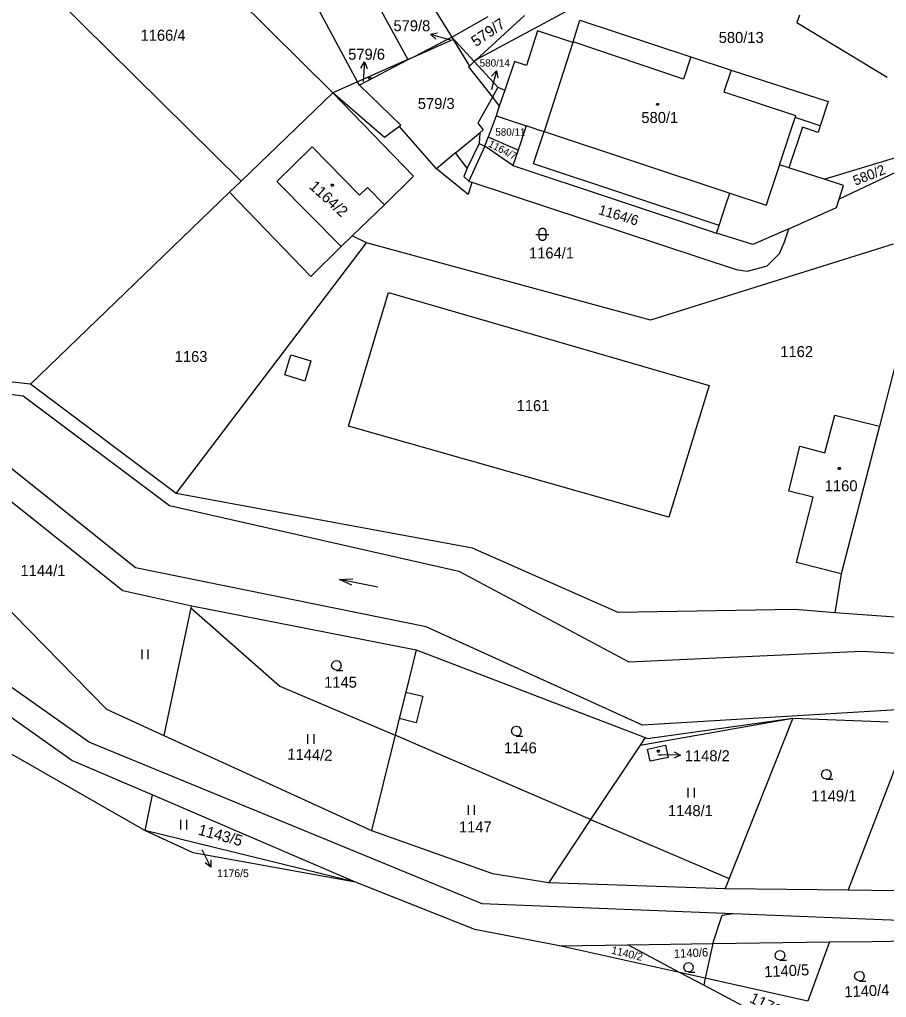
# Model space of a CAD drawing. Extents: x -621797 to -620972, y -1175539 to -1174697.
# Drawn here: x -621726 to -621592, y -1175130.5 to -1174979.5 of the extents above; entities that cross this region are included whole.
import ezdxf

# ---------------------------------------------------------------- set-up
doc = ezdxf.new("R2010")
doc.units = 0
for name, color, linetype in [('INZ mimo EON - nadz', 7, 'Continuous'), ('Rozvod plynu EON', 7, 'Continuous'), ('SDEL EON', 7, 'Continuous'), ('SDEL EON - popis', 7, 'Continuous'), ('Silnoproud EON', 7, 'Continuous'), ('Silnoproud EON - popis', 7, 'Continuous')]:
    doc.layers.add(name, color=color, linetype=linetype)

msp = doc.modelspace()

# ---------------------------------------------------------------- linework, layer by layer
at = {"layer": 'INZ mimo EON - nadz'}
for p, q in [((-621662.497, -1174981.741), (-621659.62, -1174982.59)), ((-621659.5, -1174982.63), (-621659.62, -1174982.59)), ((-621672.715, -1174986.035), (-621672.88, -1174989.03)), ((-621652.304, -1174987.405), (-621653.09, -1174990.3)), ((-621672.88, -1174989.06), (-621672.88, -1174989.03)), ((-621653.09, -1174990.32), (-621653.09, -1174990.3)), ((-621627.26, -1175093.06), (-621626.86, -1175093.07)), ((-621623.861, -1175093.125), (-621626.86, -1175093.07)), ((-621696.438, -1175110.413), (-621697.8, -1175107.74))]:
    msp.add_line(p, q, dxfattribs=at)
for points in [[(-621661.68, -1174982.504), (-621662.497, -1174981.741), (-621661.397, -1174981.545)], [(-621673.269, -1174987.005), (-621672.715, -1174986.035), (-621672.27, -1174987.061)], [(-621653.048, -1174988.239), (-621652.304, -1174987.405), (-621652.083, -1174988.501)], [(-621624.851, -1175092.607), (-621623.861, -1175093.125), (-621624.87, -1175093.607)], [(-621696.446, -1175109.295), (-621696.438, -1175110.413), (-621697.337, -1175109.749)]]:
    msp.add_lwpolyline(points, dxfattribs=at)
at = {"layer": 'Rozvod plynu EON'}
for points in [[(-621671.82, -1174988.38), (-621671.73, -1174988.53), (-621671.82, -1174988.68), (-621672, -1174988.68), (-621672.09, -1174988.53), (-621672, -1174988.38)], [(-621627.33, -1174992.44), (-621627.24, -1174992.59), (-621627.33, -1174992.74), (-621627.51, -1174992.74), (-621627.6, -1174992.59), (-621627.51, -1174992.44)], [(-621677.55, -1175004.93), (-621677.46, -1175005.08), (-621677.55, -1175005.23), (-621677.73, -1175005.23), (-621677.82, -1175005.08), (-621677.73, -1175004.93)], [(-621599.24, -1175048.68), (-621599.15, -1175048.83), (-621599.24, -1175048.98), (-621599.42, -1175048.98), (-621599.51, -1175048.83), (-621599.42, -1175048.68)], [(-621627.19, -1175092.37), (-621627.1, -1175092.52), (-621627.19, -1175092.67), (-621627.37, -1175092.67), (-621627.46, -1175092.52), (-621627.37, -1175092.37)]]:
    msp.add_lwpolyline(points, close=True, dxfattribs=at)
at = {"layer": 'SDEL EON'}
for p, q in [((-621670.65, -1175067.185), (-621676.53, -1175065.995)), ((-621707.1, -1175076.79), (-621707.1, -1175078.29)), ((-621706.1, -1175078.29), (-621706.1, -1175076.79)), ((-621681.49, -1175089.88), (-621681.49, -1175091.38)), ((-621680.49, -1175091.38), (-621680.49, -1175089.88)), ((-621622.72, -1175098.14), (-621622.72, -1175099.64)), ((-621621.72, -1175099.64), (-621621.72, -1175098.14)), ((-621656.69, -1175100.86), (-621656.69, -1175102.36)), ((-621655.69, -1175102.36), (-621655.69, -1175100.86)), ((-621701.13, -1175103.12), (-621701.13, -1175104.62)), ((-621700.13, -1175104.62), (-621700.13, -1175103.12))]:
    msp.add_line(p, q, dxfattribs=at)
msp.add_lwpolyline([(-621645.7, -1175012.17), (-621645.6, -1175011.88), (-621645.35, -1175011.7), (-621645.04, -1175011.7), (-621644.79, -1175011.88), (-621644.69, -1175012.17), (-621644.69, -1175013.17), (-621644.79, -1175013.46), (-621645.04, -1175013.64), (-621645.35, -1175013.64), (-621645.6, -1175013.46), (-621645.7, -1175013.17)], close=True, dxfattribs=at)
for points in [[(-621646.2, -1175012.67), (-621644.93, -1175012.67), (-621644.2, -1175012.67)], [(-621674.669, -1175066.882), (-621676.53, -1175065.995), (-621674.471, -1175065.902)], [(-621677.02, -1175080), (-621677.4, -1175079.9), (-621677.67, -1175079.63), (-621677.77, -1175079.26), (-621677.67, -1175078.89), (-621677.4, -1175078.62), (-621677.03, -1175078.52), (-621676.66, -1175078.62), (-621676.39, -1175078.89), (-621676.29, -1175079.27), (-621676.39, -1175079.65), (-621676.66, -1175079.92), (-621677.04, -1175080.02), (-621676.04, -1175080.02)], [(-621649.22, -1175090.14), (-621649.6, -1175090.04), (-621649.87, -1175089.77), (-621649.97, -1175089.4), (-621649.87, -1175089.03), (-621649.6, -1175088.76), (-621649.23, -1175088.66), (-621648.86, -1175088.76), (-621648.59, -1175089.03), (-621648.49, -1175089.41), (-621648.59, -1175089.79), (-621648.86, -1175090.06), (-621649.24, -1175090.16), (-621648.24, -1175090.16)], [(-621601.32, -1175096.83), (-621601.7, -1175096.73), (-621601.97, -1175096.46), (-621602.07, -1175096.09), (-621601.97, -1175095.72), (-621601.7, -1175095.45), (-621601.33, -1175095.35), (-621600.96, -1175095.45), (-621600.69, -1175095.72), (-621600.59, -1175096.1), (-621600.69, -1175096.48), (-621600.96, -1175096.75), (-621601.34, -1175096.85), (-621600.34, -1175096.85)], [(-621608.48, -1175124.77), (-621608.86, -1175124.67), (-621609.13, -1175124.4), (-621609.23, -1175124.03), (-621609.13, -1175123.66), (-621608.86, -1175123.39), (-621608.49, -1175123.29), (-621608.12, -1175123.39), (-621607.85, -1175123.66), (-621607.75, -1175124.04), (-621607.85, -1175124.42), (-621608.12, -1175124.69), (-621608.5, -1175124.79), (-621607.5, -1175124.79)], [(-621622.62, -1175126.61), (-621623, -1175126.51), (-621623.27, -1175126.24), (-621623.37, -1175125.87), (-621623.27, -1175125.5), (-621623, -1175125.23), (-621622.63, -1175125.13), (-621622.26, -1175125.23), (-621621.99, -1175125.5), (-621621.89, -1175125.88), (-621621.99, -1175126.26), (-621622.26, -1175126.53), (-621622.64, -1175126.63), (-621621.64, -1175126.63)], [(-621596.21, -1175127.99), (-621596.59, -1175127.89), (-621596.86, -1175127.62), (-621596.96, -1175127.25), (-621596.86, -1175126.88), (-621596.59, -1175126.61), (-621596.22, -1175126.51), (-621595.85, -1175126.61), (-621595.58, -1175126.88), (-621595.48, -1175127.26), (-621595.58, -1175127.64), (-621595.85, -1175127.91), (-621596.23, -1175128.01), (-621595.23, -1175128.01)]]:
    msp.add_lwpolyline(points, dxfattribs=at)
at = {"layer": 'SDEL EON - popis'}
for p, q in [((-621693.38, -1174935.2), (-621666.02, -1174985.69)), ((-621673.76, -1174989.11), (-621683.18, -1174971.62)), ((-621659.22, -1174982.2), (-621655.73, -1174985.98)), ((-621640.5, -1174983.02), (-621644.95, -1174996.81)), ((-621623.38, -1174988.68), (-621640.47, -1174982.92)), ((-621622.25, -1174985.27), (-621623.38, -1174988.68)), ((-621666.02, -1174985.69), (-621665.99, -1174985.74)), ((-621616.04, -1174987.33), (-621617.18, -1174990.67)), ((-621667.06, -1174995.79), (-621673.48, -1174989.63)), ((-621652.07, -1174989.95), (-621652.93, -1174991.5)), ((-621617.18, -1174990.67), (-621606.08, -1174994.32)), ((-621652.93, -1174991.5), (-621655.17, -1174995.52)), ((-621606.08, -1174994.32), (-621606.17, -1174994.61)), ((-621655.17, -1174995.52), (-621654.37, -1174996.53)), ((-621646.16, -1174996.41), (-621647.72, -1174995.89)), ((-621608.59, -1175001.91), (-621606.17, -1174994.61)), ((-621602.28, -1174995.89), (-621606.17, -1174994.61)), ((-621658.63, -1175000.08), (-621654.87, -1174996.98)), ((-621654.87, -1174996.98), (-621654.98, -1174998.65)), ((-621654.37, -1174996.53), (-621654.87, -1174996.98)), ((-621646.28, -1175000.82), (-621644.95, -1174996.81)), ((-621646.16, -1174996.41), (-621644.95, -1174996.81)), ((-621644.95, -1174996.81), (-621616.24, -1175006.31)), ((-621654.98, -1174998.65), (-621656.85, -1175002.46)), ((-621654.98, -1174998.65), (-621654.08, -1174999.06)), ((-621680.78, -1174999.13), (-621686.25, -1175004.53)), ((-621673.44, -1175006.62), (-621680.78, -1174999.13)), ((-621658.63, -1175000.08), (-621661.58, -1175002.54)), ((-621656.85, -1175002.46), (-621658.63, -1175000.08)), ((-621646.6, -1175001.79), (-621646.28, -1175000.82)), ((-621617.89, -1175011.29), (-621646.6, -1175001.79)), ((-621608.59, -1175001.91), (-621610.18, -1175006.73)), ((-621607.11, -1175002.39), (-621608.59, -1175001.91)), ((-621656.85, -1175002.46), (-621657.35, -1175003.72)), ((-621686.25, -1175004.53), (-621676.29, -1175014.56)), ((-621657.35, -1175003.72), (-621656.56, -1175004.45)), ((-621672.25, -1175005.45), (-621673.44, -1175006.62)), ((-621669.62, -1175008.09), (-621672.25, -1175005.45)), ((-621616.84, -1175008.11), (-621616.24, -1175006.31)), ((-621616.24, -1175006.31), (-621610.65, -1175008.16)), ((-621610.18, -1175006.73), (-621610.65, -1175008.16)), ((-621617.89, -1175011.29), (-621616.84, -1175008.11)), ((-621618.28, -1175012.47), (-621617.89, -1175011.29)), ((-621685.02, -1175034.39), (-621684.1, -1175031.27)), ((-621684.1, -1175031.27), (-621680.98, -1175032.2)), ((-621680.98, -1175032.2), (-621681.91, -1175035.34)), ((-621755.31, -1175034.04), (-621725.43, -1175037.6)), ((-621681.91, -1175035.34), (-621685.02, -1175034.39)), ((-621725.43, -1175037.6), (-621702.82, -1175054.55)), ((-621708.09, -1175064.2), (-621730.78, -1175046.05)), ((-621702.82, -1175054.55), (-621658.1, -1175064.68)), ((-621663.18, -1175073.3), (-621708.09, -1175064.2)), ((-621658.1, -1175064.68), (-621631.85, -1175078.68)), ((-621629.74, -1175088.46), (-621663.18, -1175073.3)), ((-621631.85, -1175078.68), (-621595.84, -1175077.08)), ((-621595.84, -1175077.08), (-621548.79, -1175079.5)), ((-621666.32, -1175083.37), (-621663.69, -1175084.03)), ((-621663.69, -1175084.03), (-621664.7, -1175088.12)), ((-621589.49, -1175086.06), (-621629.74, -1175088.46)), ((-621664.7, -1175088.12), (-621667.33, -1175087.47)), ((-621630.1, -1175091.59), (-621606.5, -1175087.4)), ((-621637.79, -1175103.05), (-621633.15, -1175105.02)), ((-621633.15, -1175105.02), (-621616.33, -1175112.19)), ((-621618.86, -1175122.22), (-621617.45, -1175117.83)), ((-621617.45, -1175117.83), (-621615.71, -1175117.58)), ((-621620.04, -1175127.59), (-621624.01, -1175126.7))]:
    msp.add_line(p, q, dxfattribs=at)
at = {"layer": 'Silnoproud EON'}
for p, q in [((-621688.39, -1174934.69), (-621659.22, -1174982.2)), ((-621691.74, -1175004.45), (-621728.68, -1174967.95)), ((-621628, -1174970.91), (-621655.46, -1174985.74)), ((-621677.59, -1174990.81), (-621694.08, -1174974.46)), ((-621659.22, -1174982.2), (-621653.6, -1174979.01)), ((-621647.97, -1174978.87), (-621655.46, -1174985.74)), ((-621605.5, -1174978.83), (-621605.91, -1174979.93)), ((-621640.47, -1174982.92), (-621639.4, -1174979.59)), ((-621639.4, -1174979.59), (-621622.25, -1174985.27)), ((-621605.91, -1174979.93), (-621591.92, -1174988.4)), ((-621659.22, -1174982.2), (-621665.2, -1174985.33)), ((-621659.22, -1174982.2), (-621658.99, -1174982.58)), ((-621645.96, -1174981.26), (-621647.68, -1174986.59)), ((-621640.5, -1174983.02), (-621645.96, -1174981.26)), ((-621658.99, -1174982.58), (-621665.2, -1174985.33)), ((-621658.99, -1174982.58), (-621656.48, -1174986.67)), ((-621640.5, -1174983.02), (-621640.47, -1174982.92)), ((-621665.2, -1174985.33), (-621666.02, -1174985.69)), ((-621665.2, -1174985.33), (-621665.99, -1174985.74)), ((-621622.25, -1174985.27), (-621616.04, -1174987.33)), ((-621666.02, -1174985.69), (-621673.76, -1174989.11)), ((-621665.99, -1174985.74), (-621673.48, -1174989.63)), ((-621656.48, -1174986.67), (-621656.6, -1174986.78)), ((-621656.6, -1174986.78), (-621652.93, -1174991.5)), ((-621655.73, -1174985.98), (-621656.48, -1174986.67)), ((-621655.46, -1174985.74), (-621655.73, -1174985.98)), ((-621655.73, -1174985.98), (-621652.07, -1174989.95)), ((-621649.52, -1174985.99), (-621651.02, -1174990.41)), ((-621647.68, -1174986.59), (-621649.52, -1174985.99)), ((-621616.04, -1174987.33), (-621601.05, -1174992.16)), ((-621673.76, -1174989.11), (-621677.59, -1174990.81)), ((-621673.48, -1174989.63), (-621673.76, -1174989.11)), ((-621691.74, -1175004.45), (-621677.59, -1174990.81)), ((-621669.61, -1174997.69), (-621677.59, -1174990.81)), ((-621677.59, -1174990.81), (-621665.1, -1175003.71)), ((-621652.07, -1174989.95), (-621651.02, -1174990.41)), ((-621651.02, -1174990.41), (-621651.86, -1174992.87)), ((-621652.93, -1174991.5), (-621651.86, -1174992.87)), ((-621651.86, -1174992.87), (-621652.36, -1174994.36)), ((-621601.05, -1174992.16), (-621602.28, -1174995.89)), ((-621652.36, -1174994.36), (-621653.57, -1174997.68)), ((-621652.36, -1174994.36), (-621647.72, -1174995.89)), ((-621667.06, -1174995.79), (-621667.45, -1174996.11)), ((-621667.26, -1174996.01), (-621667.06, -1174995.79)), ((-621647.72, -1174995.89), (-621648.96, -1174999.66)), ((-621602.28, -1174995.89), (-621602.62, -1174996.92)), ((-621667.45, -1174996.11), (-621669.61, -1174997.69)), ((-621661.58, -1175002.54), (-621667.26, -1174996.01)), ((-621605.04, -1174996.13), (-621607.11, -1175002.39)), ((-621602.62, -1174996.92), (-621605.04, -1174996.13)), ((-621654.08, -1174999.06), (-621653.57, -1174997.68)), ((-621648.96, -1174999.66), (-621653.57, -1174997.68)), ((-621654.08, -1174999.06), (-621656.56, -1175004.45)), ((-621649.76, -1175002.05), (-621654.08, -1174999.06)), ((-621648.96, -1174999.66), (-621649.76, -1175002.05)), ((-621601.69, -1175004.16), (-621587.34, -1174999.82)), ((-621583.76, -1174999.8), (-621599.34, -1175007.24)), ((-621656.69, -1175006.53), (-621661.58, -1175002.54)), ((-621649.76, -1175002.05), (-621618.28, -1175012.47)), ((-621601.69, -1175004.16), (-621607.11, -1175002.39)), ((-621691.74, -1175004.45), (-621693.54, -1175006.16)), ((-621665.1, -1175003.71), (-621669.62, -1175008.09)), ((-621656.09, -1175004.61), (-621656.69, -1175006.53)), ((-621656.56, -1175004.45), (-621656.09, -1175004.61)), ((-621656.09, -1175004.61), (-621615.26, -1175018.12)), ((-621598.68, -1175005.14), (-621601.69, -1175004.16)), ((-621693.54, -1175006.16), (-621724.31, -1175035.82)), ((-621681.01, -1175019.16), (-621693.54, -1175006.16)), ((-621599.34, -1175007.24), (-621598.68, -1175005.14)), ((-621599.75, -1175008.53), (-621599.34, -1175007.24)), ((-621669.62, -1175008.09), (-621674.58, -1175012.91)), ((-621607.15, -1175011.81), (-621599.75, -1175008.53)), ((-621612.68, -1175014.26), (-621618.28, -1175012.47)), ((-621607.15, -1175011.81), (-621612.68, -1175014.26)), ((-621607.83, -1175014), (-621607.15, -1175011.81)), ((-621701.81, -1175052.7), (-621672.36, -1175014)), ((-621674.58, -1175012.91), (-621676.29, -1175014.56)), ((-621672.36, -1175014), (-621674.58, -1175012.91)), ((-621628.52, -1175025.94), (-621672.36, -1175014)), ((-621608.58, -1175015.64), (-621607.83, -1175014)), ((-621676.29, -1175014.56), (-621681.01, -1175019.16)), ((-621591.02, -1175014.17), (-621628.52, -1175025.94)), ((-621610.47, -1175017.52), (-621608.58, -1175015.64)), ((-621615.26, -1175018.12), (-621613.53, -1175018.37)), ((-621613.53, -1175018.37), (-621610.47, -1175017.52)), ((-621675.17, -1175042.3), (-621668.97, -1175021.66)), ((-621668.97, -1175021.66), (-621619.46, -1175036)), ((-621587.9, -1175021.83), (-621593.12, -1175042.28)), ((-621724.31, -1175035.82), (-621753.77, -1175032.55)), ((-621701.81, -1175052.7), (-621724.31, -1175035.82)), ((-621619.46, -1175036), (-621625.65, -1175056.38)), ((-621601.54, -1175046.43), (-621600.01, -1175040.59)), ((-621600.01, -1175040.59), (-621593.12, -1175042.28)), ((-621625.65, -1175056.38), (-621675.17, -1175042.3)), ((-621593.12, -1175042.28), (-621599.04, -1175065.13)), ((-621607.14, -1175052.33), (-621605.42, -1175045.41)), ((-621605.42, -1175045.41), (-621601.54, -1175046.43)), ((-621731.94, -1175050.21), (-621710.01, -1175067.71)), ((-621656, -1175061.12), (-621701.81, -1175052.7)), ((-621603.38, -1175053.28), (-621607.14, -1175052.33)), ((-621605.95, -1175063.36), (-621603.38, -1175053.28)), ((-621742.42, -1175055.56), (-621712.54, -1175086.01)), ((-621633.5, -1175071.06), (-621656, -1175061.12)), ((-621599.04, -1175065.13), (-621605.95, -1175063.36)), ((-621599.04, -1175065.13), (-621600.03, -1175071.15)), ((-621710.01, -1175067.71), (-621699.37, -1175070.03)), ((-621717.9, -1175093.94), (-621752.9, -1175069.23)), ((-621746.97, -1175068.72), (-621715.17, -1175091.12)), ((-621699.55, -1175070.37), (-621703.72, -1175090.09)), ((-621699.37, -1175070.03), (-621699.55, -1175070.37)), ((-621699.55, -1175070.37), (-621685.79, -1175082.47)), ((-621699.37, -1175070.03), (-621665.21, -1175076.74)), ((-621606.21, -1175070.64), (-621633.5, -1175071.06)), ((-621600.03, -1175071.15), (-621606.21, -1175070.64)), ((-621582.93, -1175072.34), (-621600.03, -1175071.15)), ((-621664.69, -1175076.85), (-621666.32, -1175083.37)), ((-621665.21, -1175076.74), (-621664.69, -1175076.85)), ((-621664.69, -1175076.85), (-621629.31, -1175090.41)), ((-621706.61, -1175104.78), (-621751, -1175079.41)), ((-621685.79, -1175082.47), (-621667.97, -1175090.04)), ((-621666.32, -1175083.37), (-621667.33, -1175087.47)), ((-621712.54, -1175086.01), (-621703.72, -1175090.09)), ((-621667.33, -1175087.47), (-621667.97, -1175090.04)), ((-621628.99, -1175090.54), (-621606.5, -1175087.4)), ((-621606.5, -1175087.4), (-621616.33, -1175112.19)), ((-621606.5, -1175087.4), (-621591.78, -1175087.96)), ((-621588.05, -1175088.1), (-621597.97, -1175113.92)), ((-621715.17, -1175091.12), (-621654.58, -1175116.04)), ((-621703.72, -1175090.09), (-621671.62, -1175104.75)), ((-621667.97, -1175090.04), (-621671.62, -1175104.75)), ((-621661.32, -1175092.91), (-621667.97, -1175090.04)), ((-621629.31, -1175090.41), (-621630.1, -1175091.59)), ((-621629.31, -1175090.41), (-621628.99, -1175090.54)), ((-621630.1, -1175091.59), (-621637.79, -1175103.05)), ((-621628.98, -1175092.17), (-621626.16, -1175091.58)), ((-621628.53, -1175094.03), (-621628.98, -1175092.17)), ((-621626.16, -1175091.58), (-621625.76, -1175093.5)), ((-621705.52, -1175099.25), (-621717.9, -1175093.94)), ((-621637.79, -1175103.05), (-621661.32, -1175092.91)), ((-621625.76, -1175093.5), (-621628.53, -1175094.03)), ((-621705.52, -1175099.25), (-621706.61, -1175104.78)), ((-621674.06, -1175112.75), (-621705.52, -1175099.25)), ((-621637.79, -1175103.05), (-621644.21, -1175112.77)), ((-621699.18, -1175108.22), (-621706.61, -1175104.78)), ((-621674.06, -1175112.75), (-621706.61, -1175104.78)), ((-621671.62, -1175104.75), (-621652.94, -1175111.38)), ((-621674.06, -1175112.75), (-621699.18, -1175108.22)), ((-621652.94, -1175111.38), (-621644.21, -1175112.77)), ((-621616.33, -1175112.19), (-621616.98, -1175113.69)), ((-621655.65, -1175120.07), (-621674.06, -1175112.75)), ((-621644.21, -1175112.77), (-621616.98, -1175113.69)), ((-621616.98, -1175113.69), (-621597.97, -1175113.92)), ((-621597.97, -1175113.92), (-621590.72, -1175114)), ((-621654.58, -1175116.04), (-621615.71, -1175117.58)), ((-621615.71, -1175117.58), (-621592.73, -1175118.48)), ((-621592.73, -1175118.48), (-621583.73, -1175118.84)), ((-621642.54, -1175122.56), (-621655.65, -1175120.07)), ((-621642.54, -1175122.56), (-621631.99, -1175122.41)), ((-621624.01, -1175126.7), (-621642.54, -1175122.56)), ((-621631.99, -1175122.41), (-621618.86, -1175122.22)), ((-621624.01, -1175126.7), (-621631.99, -1175122.41)), ((-621618.86, -1175122.22), (-621620.04, -1175127.59)), ((-621618.86, -1175122.22), (-621600.87, -1175121.97)), ((-621600.87, -1175121.97), (-621604.18, -1175131.13)), ((-621600.87, -1175121.97), (-621594.26, -1175121.88)), ((-621594.26, -1175121.88), (-621584.8, -1175121.74)), ((-621620.28, -1175128.67), (-621624.01, -1175126.7)), ((-621620.04, -1175127.59), (-621620.28, -1175128.67)), ((-621606.01, -1175136.2), (-621620.28, -1175128.67)), ((-621604.18, -1175131.13), (-621620.04, -1175127.59))]:
    msp.add_line(p, q, dxfattribs=at)

# ---------------------------------------------------------------- texts
at = {"layer": 'INZ mimo EON - nadz'}
for s, height, p in [('579/8', 1.7, (-621668.22, -1174981.3)), ('579/6', 1.7, (-621675.21, -1174985.7)), ('580/14', 1.14, (-621654.898, -1174986.77)), ('1148/2', 1.7, (-621623.207, -1175094.06)), ('1176/5', 1.2, (-621695.483, -1175111.96))]:
    msp.add_text(s, height=height, dxfattribs=at).set_placement(p)
at = {"layer": 'Silnoproud EON - popis'}
for s, height, rotation, p in [('579/7', 1.7, 34.37747, (-621655.476, -1174983.77)), ('1164/7', 1.14, 332.37282, (-621653.682, -1174999.047)), ('580/2', 1.54, 21.7724, (-621596.84, -1175005.18)), ('1164/2', 1.7, 317.7051, (-621681.36, -1175005.444)), ('1164/6', 1.54, 343.25901, (-621636.662, -1175009.526)), ('1144/2', 1.7, 358.21321, (-621684.627, -1175093.792)), ('1143/5', 1.7, 344.69141, (-621698.521, -1175105.374)), ('1176/5', 0.1, 347.38431, (-621698.537, -1175107.845)), ('1140/2', 1.2, 346.52488, (-621634.64, -1175123.765)), ('1140/6', 1.3, 2.6929, (-621624.86, -1175124.446)), ('1140/5', 1.7, 2.6929, (-621610.898, -1175127.432)), ('1140/4', 1.7, 2.6929, (-621598.508, -1175130.532)), ('1176/2', 1.7, 333.9198, (-621613.337, -1175131.203))]:
    msp.add_text(s, height=height, rotation=rotation, dxfattribs=at).set_placement(p)
for s, height, p in [('1166/4', 1.7, (-621707.296, -1174982.77)), ('580/13', 1.7, (-621617.962, -1174983.11)), ('579/8', 0.1, (-621659.704, -1174982.63)), ('579/6', 0.1, (-621673.082, -1174989.06)), ('580/14', 0.1, (-621653.318, -1174990.32)), ('579/3', 1.7, (-621664.453, -1174993.31)), ('580/1', 1.7, (-621629.913, -1174995.47)), ('580/11', 1.14, (-621652.481, -1174997.44)), ('1164/1', 1.7, (-621647.277, -1175016.4)), ('1163', 1.7, (-621702.017, -1175032.39)), ('1162', 1.7, (-621608.447, -1175031.63)), ('1161', 1.7, (-621649.187, -1175039.98)), ('1160', 1.7, (-621601.574, -1175052.36)), ('1144/1', 1.7, (-621725.847, -1175065.45)), ('1145', 1.7, (-621678.927, -1175082.7)), ('1146', 1.7, (-621651.127, -1175092.84)), ('1148/2', 0.1, (-621627.467, -1175093.06)), ('1149/1', 1.7, (-621603.647, -1175100.26)), ('1148/1', 1.7, (-621625.817, -1175102.54)), ('1147', 1.7, (-621658.097, -1175105.06))]:
    msp.add_text(s, height=height, dxfattribs=at).set_placement(p)

doc.saveas('drawing.dxf')
